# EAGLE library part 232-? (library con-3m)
Zero Insertion Force Socked Source: http://www.3M.com/ehpd
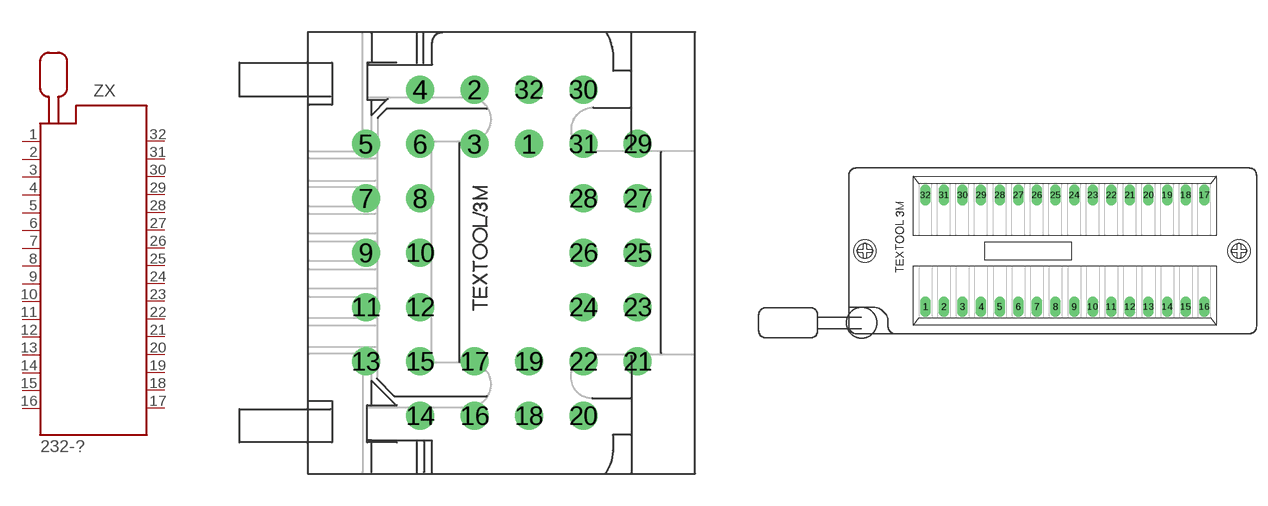
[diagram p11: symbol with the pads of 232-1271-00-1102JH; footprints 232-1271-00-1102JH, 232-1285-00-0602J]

Designator prefix ZX

## 232-1271-00-1102JH (MPN: 232-1271-00-1102JH; OC_FARNELL: unknown; OC_NEWARK: 80R8874)  [232-1271-00-1102JH]
1  1  pas
2  2  pas
3  3  pas
4  4  pas
5  5  pas
6  6  pas
7  7  pas
8  8  pas
9  9  pas
10  10  pas
11  11  pas
12  12  pas
13  13  pas
14  14  pas
15  15  pas
16  16  pas
17  17  pas
18  18  pas
19  19  pas
20  20  pas
21  21  pas
22  22  pas
23  23  pas
24  24  pas
25  25  pas
26  26  pas
27  27  pas
28  28  pas
29  29  pas
30  30  pas
31  31  pas
32  32  pas

## 232-1285-00-0602J (MF: 3M; MPN: 232-1285-00-0602J; OC_FARNELL: 9897402; OC_NEWARK: 85K7839)  [232-1285-00-0602J]
Pads as for 232-1271-00-1102JH

## Footprint 232-1271-00-1102JH (pad centres in mm)
OEM LCC Sockets 32 pol Source: http://www.3M.com/ehpd
drill 0.8 pad 1.27 round: 1 1.27,5.08; 2 -1.27,7.62; 3 -1.27,5.08; 4 -3.81,7.62; 5 -6.35,5.08; 6 -3.81,5.08; 7 -6.35,2.54; 8 -3.81,2.54; 9 -6.35,0; 10 -3.81,0; 11 -6.35,-2.54; 12 -3.81,-2.54; 13 -6.35,-5.08; 14 -3.81,-7.62; 15 -3.81,-5.08; 16 -1.27,-7.62; 17 -1.27,-5.08; 18 1.27,-7.62; 19 1.27,-5.08; 20 3.81,-7.62; 21 6.35,-5.08; 22 3.81,-5.08; 23 6.35,-2.54; 24 3.81,-2.54; 25 6.35,0; 26 3.81,0; 27 6.35,2.54; 28 3.81,2.54; 29 6.35,5.08; 30 3.81,7.62; 31 3.81,5.08; 32 1.27,7.62

## Footprint 232-1285-00-0602J (pad centres in mm)
3M TEXTOOL 32 pol. DIP Lever actuated zero insertion force mechanism Hersteller: 3M TEXTOOL Herstellerbez.: 232-1285-00-0602J Source: http://www.3M.com/ehpd
drill 0.9 long: 1 -19.05,-7.62; 2 -16.51,-7.62; 3 -13.97,-7.62; 4 -11.43,-7.62; 5 -8.89,-7.62; 6 -6.35,-7.62; 7 -3.81,-7.62; 8 -1.27,-7.62; 9 1.27,-7.62; 10 3.81,-7.62; 11 6.35,-7.62; 12 8.89,-7.62; 13 11.43,-7.62; 14 13.97,-7.62; 15 16.51,-7.62; 16 19.05,-7.62; 17 19.05,7.62; 18 16.51,7.62; 19 13.97,7.62; 20 11.43,7.62; 21 8.89,7.62; 22 6.35,7.62; 23 3.81,7.62; 24 1.27,7.62; 25 -1.27,7.62; 26 -3.81,7.62; 27 -6.35,7.62; 28 -8.89,7.62; 29 -11.43,7.62; 30 -13.97,7.62; 31 -16.51,7.62; 32 -19.05,7.62
hole 2 at 23.78,0
hole 2 at -27.28,0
